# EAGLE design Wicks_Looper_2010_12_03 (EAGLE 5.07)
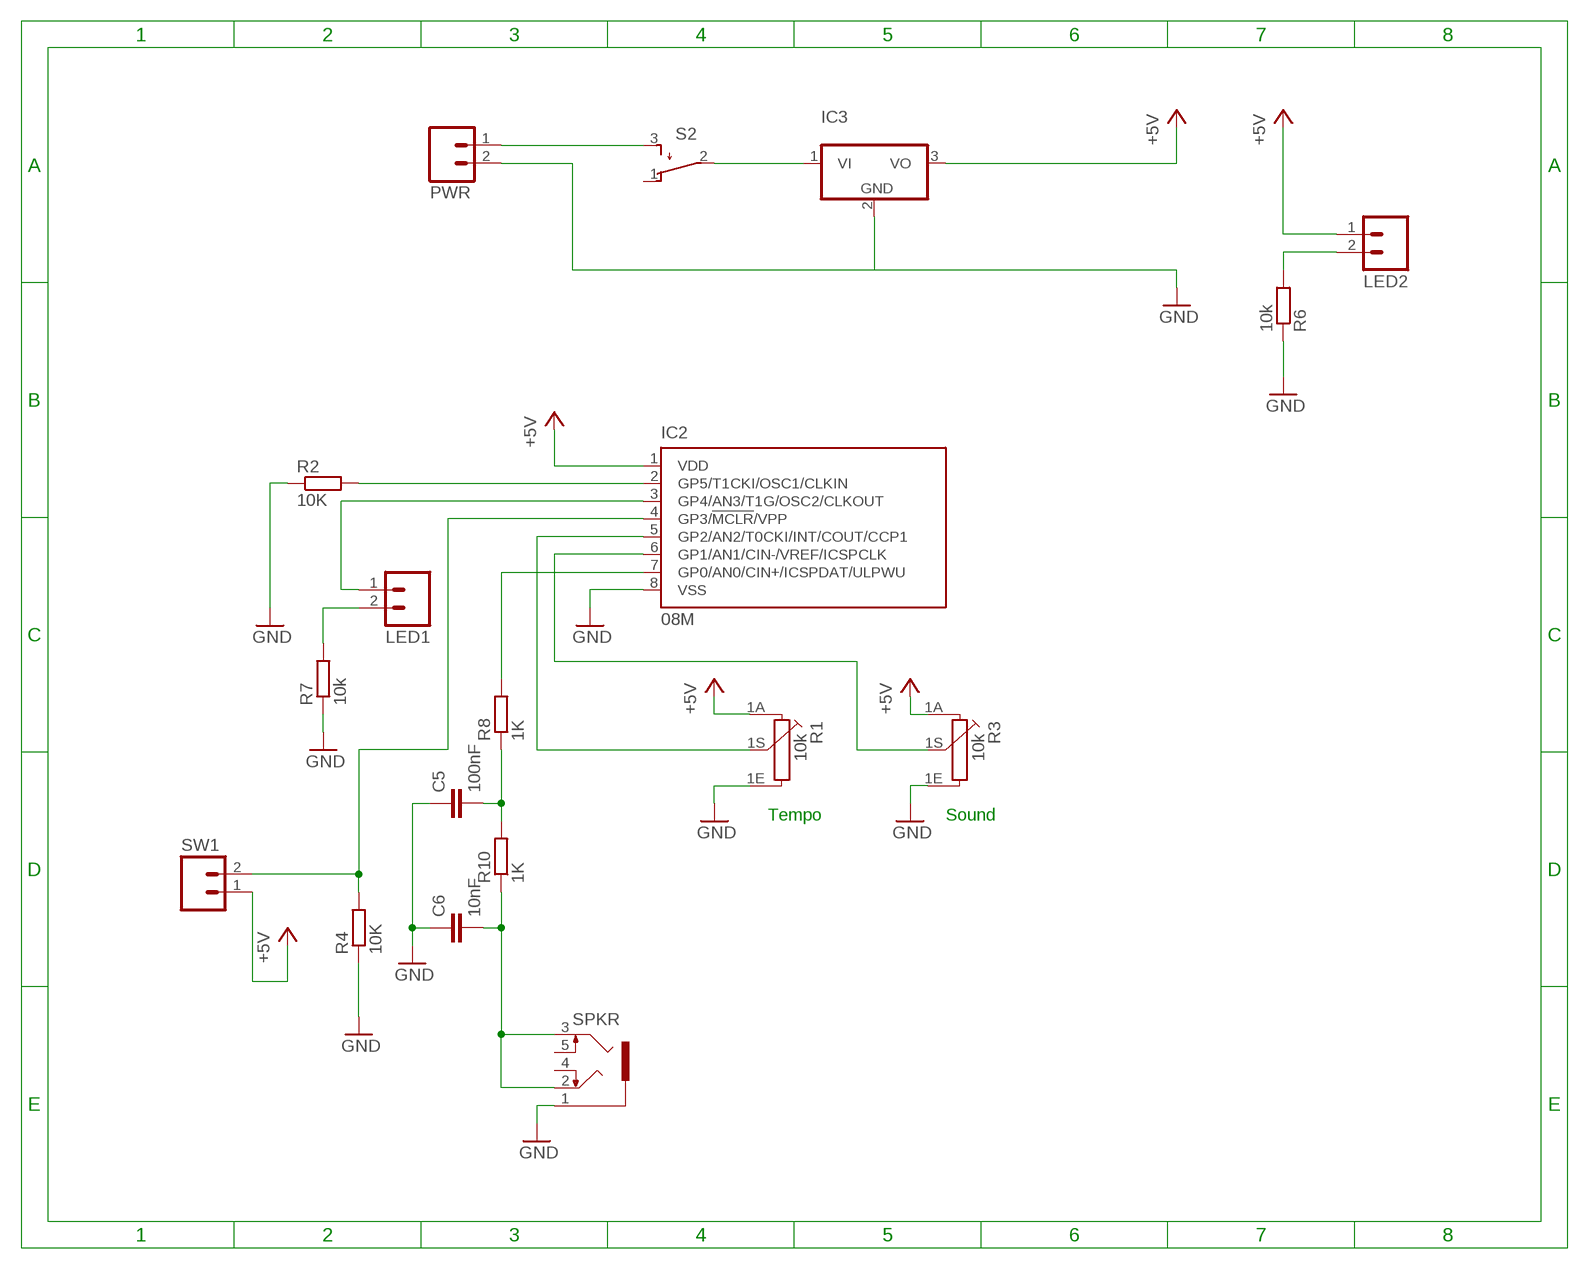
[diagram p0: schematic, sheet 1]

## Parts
C5  100nF  C5/2.5  [C5B2.5]
C6  10nF  C5/2.5  [C5B2.5]
IC2  08M  PIC12F683P  [DIL8]
IC3  786TV  [TO220V]
LED1  M02  [02P]
LED2  M02  [02P]
PWR  M02  [02P]
R1  10k  PC16S  [PC16S]
R2  10K  R-EU_0207/10  [0207/10]
R3  10k  PC16S  [PC16S]
R4  10K  R-EU_0207/10  [0207/10]
R6  10k  R-EU_0207/10  [0207/10]
R7  10k  R-EU_0207/10  [0207/10]
R8  1K  R-EU_0207/10  [0207/10]
R10  1K  R-EU_0207/10  [0207/10]
S2  TL32PO  [TL3XPO]
SPKR  1503_09  [1503_09]
SW1  M02  [02P]

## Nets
+5V: IC2.1(VDD) IC3.3(VO) LED2.1 R1.1A R3.1A SW1.1
GND: C5.1 C6.1 IC2.8(VSS) IC3.2(GND) PWR.2 R1.1E R2.1 R3.1E R4.1 R6.1 R7.1 SPKR.1
N$1: PWR.1 S2.3(S)
N$2: IC3.1(VI) S2.2(P)
N$3: IC2.2(GP5/T1CKI/OSC1/CLKIN) R2.2
N$5: IC2.4(GP3/!MCLR!/VPP) R4.2 SW1.2
N$6: IC2.7(GP0/AN0/CIN+/ICSPDAT/ULPWU) R8.2
N$7: IC2.3(GP4/AN3/T1G/OSC2/CLKOUT) LED1.1
N$8: IC2.6(GP1/AN1/CIN-/VREF/ICSPCLK) R3.1S
N$10: LED1.2 R7.2
N$11: C5.2 R8.1 R10.2
N$12: C6.2 R10.1 SPKR.2 SPKR.3
N$13: IC2.5(GP2/AN2/T0CKI/INT/COUT/CCP1) R1.1S
N$16: LED2.2 R6.2
Unconnected: S2.1(O) SPKR.4 SPKR.5

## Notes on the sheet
- Tempo | Sound

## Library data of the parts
C5 C6 = capacitor-wima:C: CAPACITOR
IC2 = microchip:PIC12F683: 8-Pin Flash-Based, 8-Bit CMOS Microcontrollers with nanoWatt Technology Source: http://ww1.microchip.com/downloads/en/DeviceDoc/41211D_.pdf
IC3 = linear:78*: Positive VOLTAGE REGULATOR Source: http://cache.national.com/ds/LM/LM78L05.pdf http://www.fairchildsemi.com/ds/LM/LM7805.pdf
LED1 LED2 PWR SW1 = con-amp-quick:M02: AMP QUICK CONNECTOR
R1 R3 = piher:PC16S: POTENTIOMETER single carbon potentiometer, 16 mm, S3ROH
R2 R4 R6-R8 R10 = resistor:R-EU_: RESISTOR, European symbol
S2 = switch:TL32PO: TINY SWITCH ON - MOM Source: http://www2.produktinfo.conrad.com/datenblaetter/700000-724999/705152-da-01-de-Subminiaturschalter_TL_36YO.pdf
SPKR = con-lumberg:1503_09: Jack connectors according to JISC 6560, 3.5 mm Klinkeneinbaukupplung nach JISC 6560, 3,5 mm, 3-polig/ stereo, abgewinkelte Ausführung, mit 2 Öffnern und Lötaugen, für Leiterplatten Rückseitenmontage Source: http://www.lumberg.com/Produkte/PDFs/1503_09.pdf

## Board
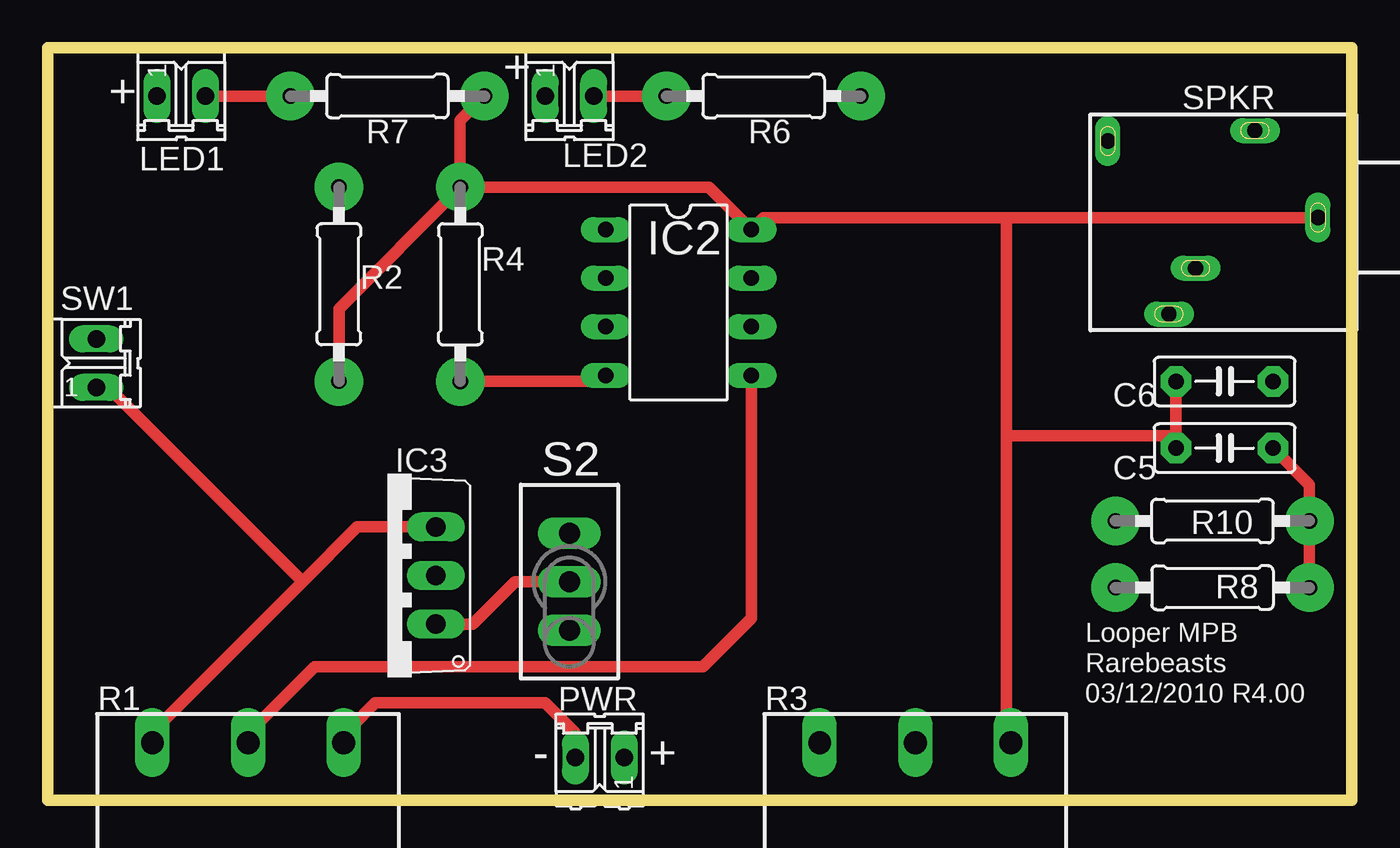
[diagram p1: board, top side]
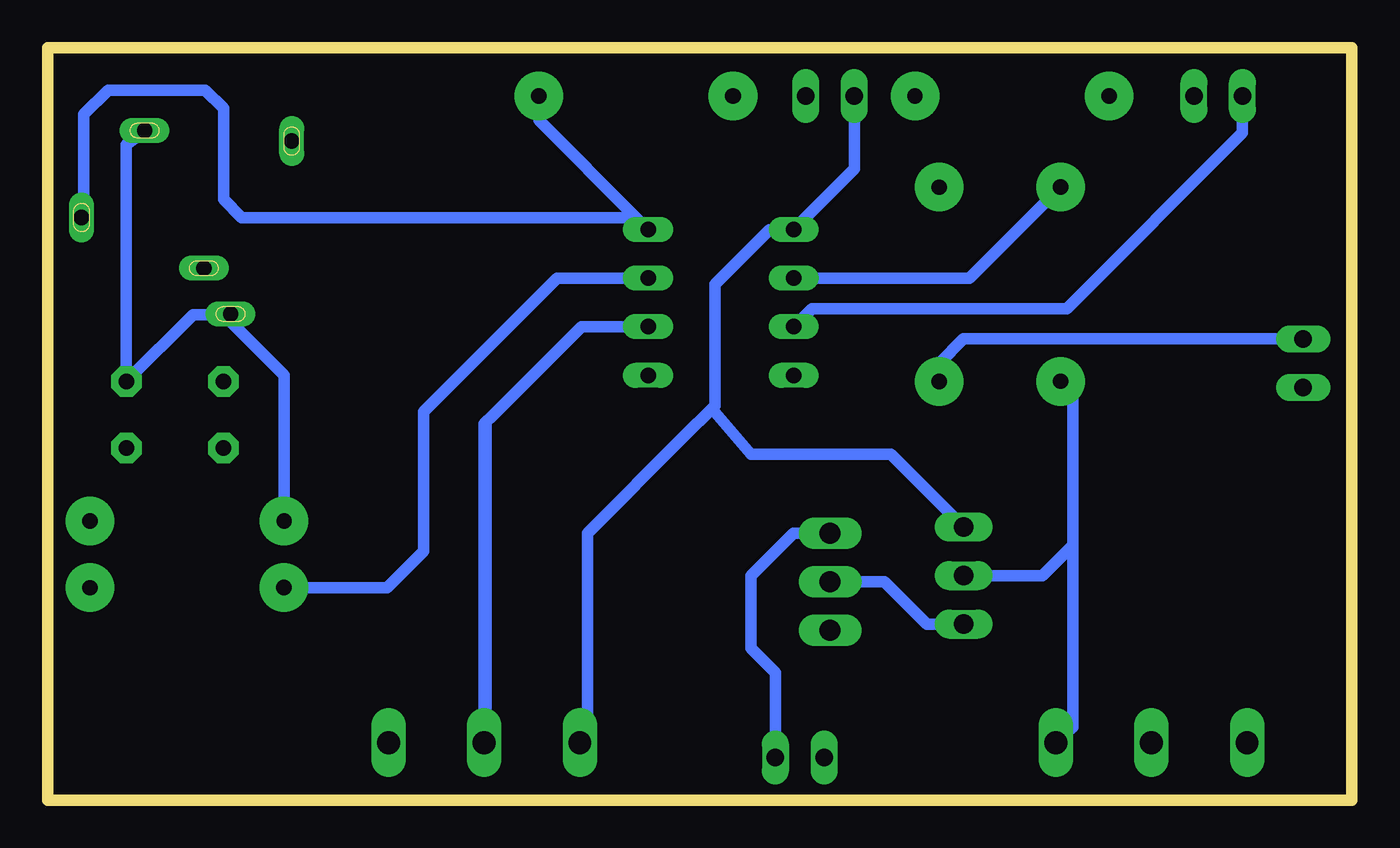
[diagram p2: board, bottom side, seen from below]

Size 68.25 x 39.36 mm. Coordinates in mm from the lower left corner, seen from the top.
Outline: 0,0 68.25,0 68.25,39.36 0,39.36 0,0
Copper layers (1*16): Top 0.0356mm / dielectric 1.5011mm / Bottom 0.0356mm
Design rules "Fusion_eagle_rule_v1.1": minimum track width 6mil, minimum drill 12mil, track to track 6mil, track to pad 6mil, pad to pad 6mil, via to via 6mil, smd to smd 0mil, copper to edge 10mil, drill to drill 10mil, minimum pad ring 10mil, minimum via ring 6mil, stop-mask expansion 2mil, vias tented up to drill 100mil, thermal gap 10mil

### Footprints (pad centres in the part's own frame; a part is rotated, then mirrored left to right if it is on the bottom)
C5B2.5 = drill 0.813 pad 1.6 octagon: 1 -2.54,0; 2 2.54,0
DIL8 = drill 0.813 long: 1 -3.81,-3.81; 2 -1.27,-3.81; 3 1.27,-3.81; 4 3.81,-3.81; 5 3.81,3.81; 6 1.27,3.81; 7 -1.27,3.81; 8 -3.81,3.81
TO220V = drill 1.016 long: 1 -2.54,-2.54; 2 0,-2.54; 3 2.54,-2.54
02P = drill 0.914 long: 1 -1.27,0; 2 1.27,0
PC16S = drill 1.2 long: 1A -5,6.5; 1E 5,6.5; 1S 0,6.5
0207/10 = drill 0.8 pad 2.54 round: 1 -5.08,0 | drill 0.813 pad 2.54 round: 2 5.08,0
TL3XPO = drill 1.1 pad 1.422 long: 1 -2.54,0; 2 0,0; 3 2.54,0
1503_09 = drill 0.8 pad 1.2 long: 1 0,-2.1; 2 -4.55,-5.4; 3 5.05,-9.9; 4 -4,-13.1; 5 2.65,-8.5

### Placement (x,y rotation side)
C5  61.59,18.42 0 top
C6  61.59,21.91 0 top
IC2  33.02,26.04 270 top
IC3  17.78,11.75 90 top
LED1  6.99,36.83 0 top
LED2  27.3,36.83 0 top
PWR  28.89,2.22 180 top
R1  10.48,-3.49 0 top
R2  15.24,26.99 90 top
R3  45.4,-3.49 0 top
R4  21.59,26.99 270 top
R6  37.47,36.83 180 top
R7  17.78,36.83 180 top
R8  60.96,11.11 180 top
R10  60.96,14.6 0 top
S2  27.3,11.43 90 top
SPKR  68.58,30.48 270 top
SW1  2.54,22.86 90 top

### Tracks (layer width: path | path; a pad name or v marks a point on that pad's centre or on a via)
+5V
  Top 0.61: IC3.3 16.19,14.29 13.34,11.43 | 13.34,11.43 3.17,21.59 SW1.1 | 13.34,11.43 5.72,3.81 R1.1A
  Bottom 0.61: LED2.1 26.04,33.02 IC2.1 30.48,29.85 33.34,26.99 33.34,20.64 33.5,20.48 | IC3.3 24.13,18.1 31.43,18.1 33.5,20.48 | 33.5,20.48 34.93,19.05 40.01,13.97 40.01,3.81 R3.1A
GND
  Top 0.61: R2.1 15.24,25.72 R4.1 | R7.1 21.59,35.56 R4.1 | R4.1 34.61,32.07 IC2.8 37.47,30.48 50.17,30.48 | PWR.2 27.62,3.49 26.04,5.08 17.14,5.08 15.88,3.81 R1.1E | 59.05,19.05 C6.1 | 50.17,30.48 SPKR.1 66.67,30.48 | 50.17,30.48 50.17,19.05 | 50.17,19.05 50.17,3.81 R3.1E | 50.17,19.05 59.05,19.05 | 59.05,19.05 C5.1
  Bottom 0.61: 14.61,13.33 16.19,11.75 IC3.2 | 14.61,13.33 14.61,21.59 R2.1 | 37.47,30.48 42.55,35.56 R6.1 | 14.61,13.33 14.61,3.81 R1.1E | IC2.8 37.47,30.48 | 37.47,30.48 58.1,30.48 59.05,31.43 59.05,36.2 60.01,37.15 65.09,37.15 66.36,35.88 66.36,30.48 66.67,30.48
N$1
  Bottom 0.61: PWR.1 30.16,6.67 31.43,7.94 31.43,11.75 29.21,13.97 S2.3
N$2
  Top 0.61: IC3.1 22.22,9.21 24.45,11.43 S2.2
  Bottom 0.61: S2.2 24.45,11.43 22.22,9.21 IC3.1
N$3
  Bottom 0.61: IC2.2 20,27.3 R2.2
N$5
  Top 0.61: IC2.4 28.89,21.91 R4.2
  Bottom 0.61: SW1.2 20.32,24.13 21.59,22.86 R4.2
N$6
  Bottom 0.61: R8.2 50.48,11.11 48.58,13.02 48.58,20.32 41.59,27.3 IC2.7
N$7
  Bottom 0.61: IC2.3 28.26,25.72 14.92,25.72 5.72,34.92 LED1.1
N$8
  Bottom 0.152: R3.1S 45.09,3.81 45.09,20.32 44.93,20.16
  Bottom 0.61: 45.4,3.18 45.4,19.69 44.93,20.16 40.32,24.77 IC2.6
N$10
  Top 0.61: LED1.2 R7.2
N$11
  Top 0.61: R8.1 R10.2 66.04,16.51 C5.2
N$12
  Bottom 0.61: 59.05,25.4 60.64,25.4 C6.2 64.14,34.29 SPKR.2 | 59.05,25.4 SPKR.3 | 59.05,25.4 55.88,22.23 R10.1
N$13
  Top 0.61: IC2.5 36.83,9.53 34.29,6.98 13.97,6.98 10.8,3.81 R1.1S
N$16
  Top 0.61: LED2.2 R6.2

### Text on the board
tNames: + | + | Looper MPB | Rarebeasts | 03/12/2010 R4.00 | - | +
